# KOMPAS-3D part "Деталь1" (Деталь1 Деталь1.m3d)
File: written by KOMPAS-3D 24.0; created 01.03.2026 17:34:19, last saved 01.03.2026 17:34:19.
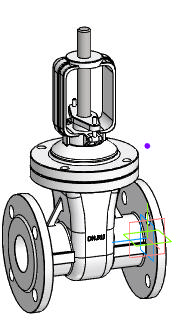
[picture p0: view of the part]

Document properties: Автор: R2D2; Полное имя файла: E:\Работа\Зайцев\GVWR3131M-2W-F-S Задвижка клиновая с выдвижным штоком DN.ru Ду50-200 Ру63\DN50\исходные материалы\Деталь1 Деталь1.m3d

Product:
- Body: Твердое тело1  | qty 1
- Part/product: Деталь1
    additional columns: Типовые

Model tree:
1. Твердое тело1  (labels: Твердое тело1)
2. Точка:1
     Y = 130.5; Координата Y = 130.5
